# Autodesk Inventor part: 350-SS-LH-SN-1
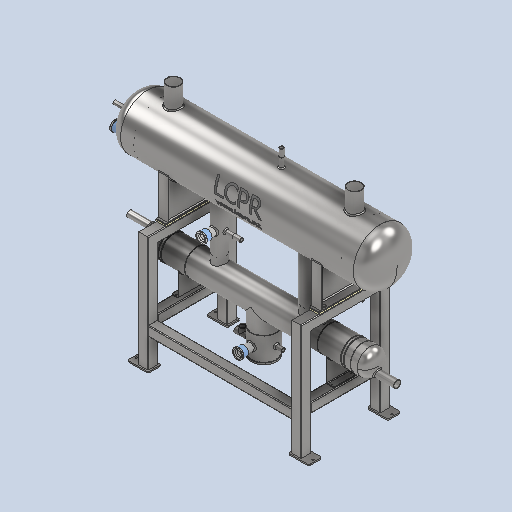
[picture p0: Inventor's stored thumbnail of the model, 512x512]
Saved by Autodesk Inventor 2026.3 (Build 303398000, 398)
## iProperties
Created: 2026-05
Part Number: 350-SS-LH-SN-1
Material: Generic
Document SubType Name: Modeling
Designer: rva
Density: 1 g/cm^3
Appearance: Default
Author: rva
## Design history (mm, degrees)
derived "350-SS-LH-SN.iam"
body "Solid1"
node "LPR-350-Frame Assembly.iam:1::LCPR-SS-350-135 x 85 Frame Foo"
node "LPR-350-Frame Assembly.iam:1::LCPR-SS-350-135 x 85 Frame Foo"
node "LPR-350-Frame Assembly.iam:1::LCPR-SS-350-135 x 85 Frame Foo"
node "LPR-350-Frame Assembly.iam:1::LCPR-SS-350-135 x 85 Frame Foo"
node "Sub-150-75-1171-30-40-32-SS-LH.iam:1::ISO 5251 Equal Tee DN1"
node "Sub-150-75-1171-30-40-32-SS-LH.iam:1::150-30-SS-Hole Sub Coo"
node "Sub-150-75-1171-30-40-32-SS-LH.iam:1::150-30-SS-Hole Sub Coo"
node "Sub-150-75-1171-30-40-32-SS-LH.iam:1::150 mm-SS- Subcooler L"
node "Sub-150-75-1171-30-40-32-SS-LH.iam:1::LCPR-150-SS-Blank Plat"
node "Sub-150-75-1171-30-40-32-SS-LH.iam:1::150 mm-SS- Subcooler L"
node "Sub-150-75-1171-30-40-32-SS-LH.iam:1::1-2 Inch NPT Socket - "
node "Sub-150-75-1171-30-40-32-SS-LH.iam:1::1-2 Inch NPT Socket - "
node "Sub-150-75-1171-30-40-32-SS-LH.iam:1::1-2 Inch NPT Socket - "
node "Sub-150-75-1171-30-40-32-SS-LH.iam:1::H1100-R.ipt:1"
node "Sub-150-75-1171-30-40-32-SS-LH.iam:1::H1100-R.ipt:2"
node "Sub-150-75-1171-30-40-32-SS-LH.iam:1::Welds"
node "Nylon Heat Tranfer Spacer 348x65.ipt:1"
node "Nylon Heat Tranfer Spacer 348x65.ipt:2"
node "AS 1111 - Metric M10 x 100:1"
node "AS 1112 (4) - Metric M10:1"
node "AS 1237 (4.1) 10 mm:1"
node "AS 1237 (4.1) 10 mm:2"
node "AS 1111 - Metric M10 x 100:2"
node "AS 1112 (4) - Metric M10:2"
node "AS 1237 (4.1) 10 mm:3"
node "AS 1237 (4.1) 10 mm:4"
node "AS 1111 - Metric M10 x 100:3"
node "AS 1112 (4) - Metric M10:3"
node "AS 1237 (4.1) 10 mm:5"
node "AS 1237 (4.1) 10 mm:6"
node "AS 1111 - Metric M10 x 100:4"
node "AS 1112 (4) - Metric M10:4"
node "AS 1237 (4.1) 10 mm:7"
node "AS 1237 (4.1) 10 mm:8"
node "350-SS-SHELL-SN-WELD.iam:1::LCPR-LOGO.ipt:1"
node "350-SS-SHELL-SN-WELD.iam:1::LCPR-SS-350-Leg Assembly.iam:1::"
node "350-SS-SHELL-SN-WELD.iam:1::LCPR-SS-350-Leg Assembly.iam:2::"
node "350-SS-SHELL-SN-WELD.iam:1::350 mm-SS- Dome End Cap.ipt:1"
node "350-SS-SHELL-SN-WELD.iam:1::350 mm-SS- Dome End Cap.ipt:2"
node "350-SS-SHELL-SN-WELD.iam:1::H1100-R.ipt:1"
node "350-SS-SHELL-SN-WELD.iam:1::Welds"
node "350-SS-LH-SN.iam_Bodies"
